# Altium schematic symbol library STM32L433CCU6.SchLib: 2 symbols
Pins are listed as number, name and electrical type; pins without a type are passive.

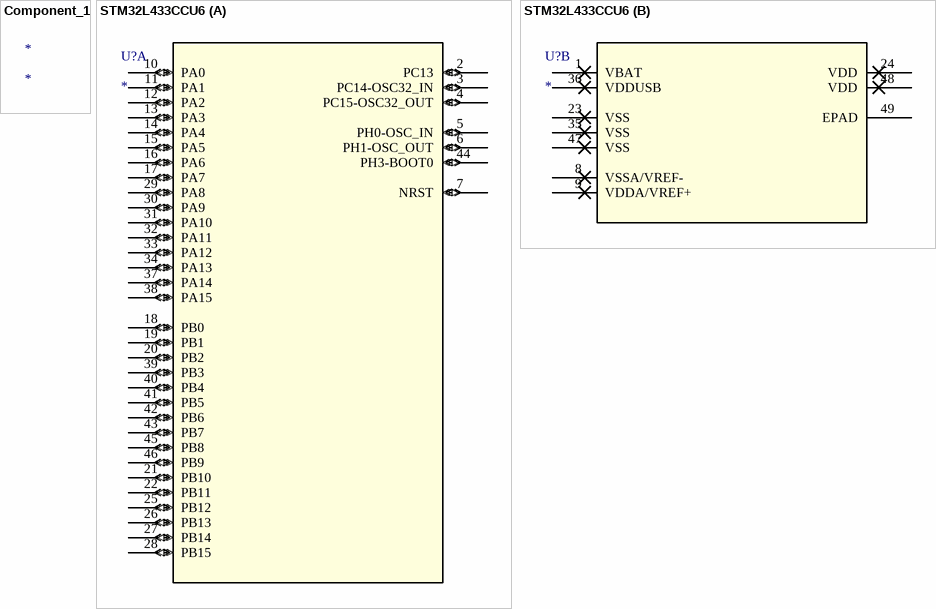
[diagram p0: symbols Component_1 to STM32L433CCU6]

## Component_1
designator *

## STM32L433CCU6
designator U?
No Description Available; Mfr_Name: STMicroelectronics
footprint UFQFPN48-7x7mm
part A pins: 2 PC13 (io), 3 PC14-OSC32_IN (io), 4 PC15-OSC32_OUT (io), 5 PH0-OSC_IN (io), 6 PH1-OSC_OUT (io), 7 NRST (io), 10 PA0 (io), 11 PA1 (io), 12 PA2 (io), 13 PA3 (io), 14 PA4 (io), 15 PA5 (io), 16 PA6 (io), 17 PA7 (io), 18 PB0 (io), 19 PB1 (io), 20 PB2 (io), 21 PB10 (io), 22 PB11 (io), 25 PB12 (io), 26 PB13 (io), 27 PB14 (io), 28 PB15 (io), 29 PA8 (io), 30 PA9 (io), 31 PA10 (io), 32 PA11 (io), 33 PA12 (io), 34 PA13 (io), 37 PA14 (io), 38 PA15 (io), 39 PB3 (io), 40 PB4 (io), 41 PB5 (io), 42 PB6 (io), 43 PB7 (io), 44 PH3-BOOT0 (io), 45 PB8 (io), 46 PB9 (io)
part B pins: 1 VBAT (power), 8 VSSA/VREF- (power), 9 VDDA/VREF+ (power), 23 VSS (power), 24 VDD (power), 35 VSS (power), 36 VDDUSB (power), 47 VSS (power), 48 VDD (power), 49 EPAD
